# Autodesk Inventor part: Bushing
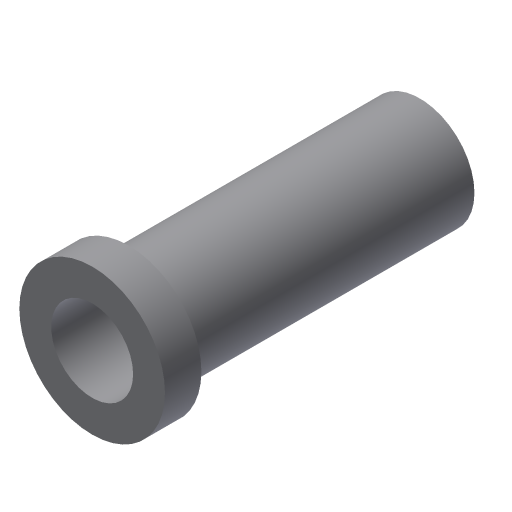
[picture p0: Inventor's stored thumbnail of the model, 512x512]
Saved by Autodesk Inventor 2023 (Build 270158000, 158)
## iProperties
Created: 2002-02
Part Number: Bushing
Document SubType Name: Modeling
Designer: ***
Density: 1 g/cm^3
Material: Generic
Appearance: Default
Control State: 0
Master: False
Checked Out: False
Shininess: 77.0
Length Units: 11269
Angle Units: 11279
Time Units: 11290
Mass Units: 11283
Length Display Precision: 3
Angle Display Precision: 2
Density: 0.0
Volumn: 0.0
Area: 0.0
PropertySet Name: Model Information
Author: ***
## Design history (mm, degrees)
sketch "Sketch1"
  geometry: L1 (6.25, 50.44)-(6.25, 5.44); L2 (6.25, 5.44)-(10.625, 5.44); L3 (10.625, 5.44)-(10.625, 10.44); L4 (10.625, 10.44)-(8.125, 10.44); L5 (8.125, 10.44)-(8.125, 50.44); L6 (8.125, 50.44)-(6.25, 50.44); L7 (0.625, 34.884)-(0.625, 0)
  constraints: 14 end point, 4 parallel, 2 perpendicular, 1 vertical
  dimensions: "d0" = 20 diameter of L3 L7; "d1" = 11.25 diameter of L1 L7; "d2" = 15 diameter of L5 L7; "d4" = 5 distance of L2.end L3.end; "d5" = 45 distance of L1.start L1.end
revolve "Revolution1" sketch "Sketch1" stored, may be unused: angle "d3" = 90 deg
body "Solid1"
